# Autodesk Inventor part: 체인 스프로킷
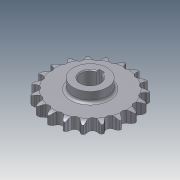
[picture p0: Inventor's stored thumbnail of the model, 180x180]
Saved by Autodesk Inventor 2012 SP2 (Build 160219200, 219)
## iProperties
Created: 2013-01
Part Number: 체인 스프로킷
Material: 강
Document SubType Name: Modeling
Designer: KYOUNG IL JANG
Density: 1 g/cm^3
CustomPartVersion: 1
Company: 한국ATC센터
Author: KYOUNG IL JANG
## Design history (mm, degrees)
sketch "이론적 톱니 프로파일"
  geometry: L1 (0, 0)-(0, 45.567); L2 (0, 0)-(14.795, 43.098); L3 (0, 45.567)-(14.795, 43.098); L4 (0, 45.567)-(5.661, 50.015); L5 (5.661, 50.015)-(-5.141, 45.406); L6 (-12.428, 43.493)-(-5.573, 46.417); L7 (-5.141, 45.406)-(-5.573, 46.417); L8 (5.573, 46.417)-(5.141, 45.406); L9 (0, 0)-(8.138, 48.771); A1 r 45.567 centre (0, 0) between (0, 45.567) and (14.795, 43.098); A2 r 49.445 centre (0, 0) between (7.302, 48.903) and (-7.302, 48.903); A3 r 4.545 centre (0, 45.567) between (-3.574, 42.758) and (3.574, 42.758); A4 r 7.453 centre (12.428, 43.493) between (7.302, 48.903) and (5.573, 46.417); A5 r 7.453 centre (-12.428, 43.493) between (-5.573, 46.417) and (-7.302, 48.903); A6 r 11.745 centre (5.661, 50.015) between (-5.141, 45.406) and (-3.574, 42.758); A7 r 11.745 centre (-5.661, 50.015) between (3.574, 42.758) and (5.141, 45.406); 2 further points
  constraints: 18 end point, 15 point on circle, 7 centre point, 3 coincident, 3 point on line, 3 symmetric about line, 3 tangent, 1 equal radius, 1 midpoint, 1 parallel, 1 vertical, 1 other
  dimensions: "d0" = 91.13301 diameter of A1 (computed from da_p, da_z); "d2" = 18.9474 deg angle of L2 L1 (computed from da_z); "d3" = 4.545 radius of A3 (= 0.5 x da_Dr + da_SC); "d10" = 128.158 deg angle of L4 L1 (computed from da_z); "d11" = 15.0526 deg angle of L5 L4 (computed from da_z); "d12" = 7.2 distance of L3.start L4.end (= 0.8 x da_Dr); "d13" = 11.745 distance of L4.end L5.end (= 1.3 x da_Dr + da_SC); "d14" = 12.6 distance of A4.centre L1.end (= 1.4 x da_Dr); "d23" = 4.5 distance from line of L9.end L3 (= da_Ha)
sketch "톱니 프로파일"
  geometry: L1 (0, 0)-(0, 45.567); L2 (0, 45.567)-(4.203, 43.837); L3 (0, 45.567)-(-4.203, 43.837); A1 r 4.545 centre (0, 45.567) between (-4.203, 43.837) and (4.203, 43.837); A2 r 22.68 centre (25.176, 35.206) between (7.12, 48.93) and (4.203, 43.837); A3 r 22.68 centre (-25.176, 35.206) between (-4.203, 43.837) and (-7.12, 48.93); A4 r 49.445 centre (0, 0) between (-7.12, 48.93) and (7.12, 48.93) reference; 1 further point
  constraints: 9 point on circle, 6 end point, 3 centre point, 2 tangent, 1 coincident, 1 equal radius, 1 vertical, 1 other
  dimensions: "d44" = 135.263 deg angle of L3 L2 (= da_Alfa); "d45" = 22.68 radius of A2 (= da_Re); "d46" = 4.545 radius of A1 (= da_Ri)
sketch "단면 프로파일"
  geometry: L1 (49.445, 0)-(-49.445, 0) reference; L2 (33.265, 6.65)-(-33.265, 6.65); L3 (-33.265, 6.65)-(-33.265, -6.65); L4 (-33.265, -6.65)-(33.265, -6.65); L5 (33.265, -6.65)-(33.265, 6.65); L6 (33.265, 6.65)-(49.445, 6.65); L7 (49.445, 6.65)-(49.445, -6.65); L8 (49.445, -6.65)-(33.265, -6.65); L9 (33.265, -6.65)-(33.265, 6.65); L10 (42.183, 6.65)-(0, 6.65); L11 (0, 6.65)-(0, -6.65); L12 (0, -6.65)-(42.183, -6.65); L13 (0, 6.65)-(0, -6.65); L14 (49.445, 4.775)-(49.445, -4.775); A1 r 15 centre (42.183, -8.35) between (49.445, 4.775) and (42.183, 6.65); A2 r 15 centre (42.183, 8.35) between (42.183, -6.65) and (49.445, -4.775); 2 further points
  constraints: 26 end point, 7 midpoint, 5 perpendicular, 4 parallel, 4 point on circle, 3 point on line, 3 symmetric about line, 2 centre point, 2 horizontal, 2 tangent, 1 collinear, 1 other
  dimensions: "d30" = 13.3 distance between parallel lines of L8 L6 (= da_Bf); "d31" = 66.53007 distance between parallel lines of L3 L5 (= da_Ds); "d32" = 13.3 distance between parallel lines of L4 L2 (= da_Bs); "d33" = 1.875 distance from line of L14.start L6 (= da_Ba); "d34" = 15 radius of A1 (= da_Rx); "d43" = 6.65 distance between parallel lines of L4 L1 (computed from da_k, da_pt, da_Bs)
revolve "슈라우드" stored, may be unused: angle "d36" = 90 deg
revolve "스트랜드" stored, may be unused: angle "d37" = 90 deg
extrude "이론적 톱니" cut sketch "이론적 톱니 프로파일" stored distance "d18" = 10; taper "d19" = 0 deg; dims "d49" = 0, "form_type" = 0 [user parameter]
extrude "톱니" cut sketch "톱니 프로파일" stored distance "d47" = 10; taper "d48" = 0 deg; dims "d50" = 10, "form_type" = 0 [user parameter]
node "타이밍 평면"
node "작업 평면3"
sketch "스케치5"
  geometry: C1 r 20 at (0, -45.567); 1 further point
  constraints: 1 centre point, 1 coincident
  dimensions: "d52" = 40 diameter of C1
extrude "돌출4" join sketch "스케치5" stored distance "d53" = 10; taper "d54" = 0 deg
sketch "스케치6"
  geometry: L1 (3, 10.583)-(3, 13.8); L2 (3, 13.8)-(-3, 13.8); L3 (-3, 13.8)-(-3, 10.583); A1 r 11 centre (0, 0) between (3, 10.583) and (-3, 10.583); 1 further point
  constraints: 6 end point, 2 parallel, 2 point on circle, 1 centre point, 1 coincident, 1 perpendicular, 1 vertical
  dimensions: "d55" = 22 diameter of A1; "d56" = 24.8 dimension on A1 L2 (computed from d55); "d57" = 6 distance of L1.end L2.end
extrude "돌출5" cut sketch "스케치6" stored distance "d58" = 10; taper "d59" = 0 deg
fillet "모깎기2" dims "d60" = 3
chamfer "모따기1" distance "d61" = 1; stored, may be unused: second distance "d62" = 2, angle "d63" = 45 deg
body "Solid1"
pattern_linear "스트랜드 패턴" dims "d40" = 24 (= da_pt)
pattern_circular "톱니 패턴" dims angle "d21" = 360 deg
other parameters: "da_p" = 15 [user parameter; used in 1 equation term], "da_Dr" = 9 [user parameter; used in 4 equation terms], "da_SC" = 0.045 [user parameter; used in 2 equation terms], "da_Ha" = 4.5 [user parameter; used in 1 equation term], "da_pt" = 24 [user parameter; used in 2 equation terms], "da_Bf" = 13.3 [user parameter; used in 1 equation term], "d28" = 0, "d29" = 0, "da_Ba" = 1.875 [user parameter; used in 1 equation term], "da_Rx" = 15 [user parameter; used in 1 equation term], "da_Ra" = 0.6 [user parameter], "da_Bs" = 13.3 [user parameter; used in 2 equation terms], "da_Ds" = 66.53007 [user parameter; used in 1 equation term], "d42" = 0, "da_Re" = 22.68 [user parameter; used in 1 equation term], "da_Ri" = 4.545 [user parameter; used in 1 equation term], "da_Alfa" = 135.263 deg [user parameter; used in 1 equation term], "d51" = -25
